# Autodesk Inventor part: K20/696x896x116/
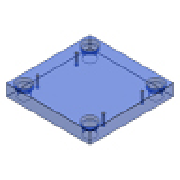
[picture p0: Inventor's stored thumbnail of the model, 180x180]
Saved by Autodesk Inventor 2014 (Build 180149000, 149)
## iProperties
IsCustomPart: 1
Created: 2009-11
Part Number: K20/696x896x116/
Material: DIN 1.1730
Description: Cavity Plate
Document SubType Name: Modeling
Designer: gaom
Standard Revision: 1
Manufacturer: HASCO
Language: en-US
Size Designation: 696x896x116/
Categories: <MemberInstance><Categories><Category DisplayName="Mold" InternalName="349578f2-f4d4-4954-8c09-8e99297a61c0" Mnemonic="MOLD"><Category DisplayName="Mold Plates"
Density: 7.82 g/cm^3
Appearance: Clear - Blue
Author: gaom
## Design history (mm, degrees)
sketch "Sketch1"
  geometry: L1 (-348, 448)-(348, 448); L2 (348, 448)-(348, -448); L3 (348, -448)-(-348, -448); L4 (-348, -448)-(-348, 448); 3 further points
  constraints: 8 end point, 2 midpoint, 2 parallel, 1 horizontal, 1 horizontal alignment, 1 perpendicular, 1 vertical alignment
  dimensions: "d126" = 696 distance between parallel lines of L2 L4 (= TW_); "d127" = 896 distance between parallel lines of L3 L1 (= TL)
extrude "Extrusion1" new body sketch "Sketch1" distance "d20" = 116 (= H_); taper "d30" = 0 deg
sketch "Sketch2"
  geometry: 6 further points
  dimensions: "d128" = 296 horizontal distance of point (0, 0) point (-296, 337) (= 0.5 x S1_W); "d129" = 337 vertical distance of point (0, 0) point (-296, 337) (= 0.5 x S1_L); "d130" = 396 vertical distance of point (0, 0) point (-296, 396) (= 0.5 x GP_L); "d131" = 296 horizontal distance of point (0, 0) point (-296, 396) (= 0.5 x GP_W); "d161" = 296 horizontal distance of point (0, 0) point (-296, -396) (= 0.5 x GP_W); "d162" = 396 vertical distance of point (0, 0) point (-296, -396) (= 0.5 x GP_L); "d163" = 296 horizontal distance of point (0, 0) point (296, 396) (= 0.5 x GP_W); "d164" = 396 vertical distance of point (0, 0) point (296, 396) (= 0.5 x GP_L); "d165" = 296 horizontal distance of point (296, -396) point (0, 0) (= 0.5 x GP_W); "d166" = 396 vertical distance of point (0, 0) point (296, -396) (= 0.5 x GP_L)
feature "Sculpt6"
workplane "Work Plane2"
workplane "Work Plane3"
workplane "Work Plane4"
workplane "Work Plane5"
workplane "Work Plane6"
workplane "Work Plane7"
workplane "Work Plane8"
workplane "Work Plane9"
feature "Sculpt109"
feature "Sculpt110"
feature "Sculpt111"
feature "Sculpt112"
feature "Sculpt113"
feature "Sculpt114"
feature "Sculpt115"
feature "Sculpt116"
feature "Sculpt117"
feature "Sculpt118"
feature "Sculpt119"
feature "Sculpt120"
feature "Sculpt121"
feature "Sculpt122"
feature "Sculpt123"
feature "Sculpt124"
feature "Sculpt125"
feature "Sculpt126"
feature "Sculpt127"
feature "Sculpt128"
sketch "Sketch3"
  geometry: L1 (-211.617, 350)-(211.617, 350); L2 (-220, -341.617)-(-220, 341.617); L3 (211.617, -350)-(-211.617, -350); L4 (220, 341.617)-(220, -341.617); A1 r 6 centre (216.464, 346.464) between (220, 341.617) and (211.617, 350); A2 r 6 centre (-216.464, 346.464) between (-211.617, 350) and (-220, 341.617); A3 r 6 centre (-216.464, -346.464) between (-220, -341.617) and (-211.617, -350); A4 r 6 centre (216.464, -346.464) between (211.617, -350) and (220, -341.617)
  constraints: 8 end point, 8 point on circle, 4 centre point
extrude "Extrusion2" cut sketch "Sketch3" distance "d189" = 120; taper "d190" = 0 deg
feature "Sculpt133"
thread "Thread1" dims "d191" = 0, "d192" = 0
feature "Sculpt134"
thread "Thread2" dims "d193" = 0, "d194" = 0
feature "Sculpt135"
thread "Thread3" dims "d195" = 0, "d196" = 0
feature "Sculpt136"
thread "Thread4" dims "d197" = 0, "d198" = 0
feature "Sculpt137"
thread "Thread5" dims "d199" = 0, "d200" = 0
feature "Sculpt138"
thread "Thread6" dims "d201" = 0, "d202" = 0
feature "Sculpt139"
thread "Thread7" dims "d203" = 0, "d204" = 0
feature "Sculpt140"
thread "Thread8" dims "d205" = 0, "d206" = 0
feature "Sculpt141"
body "Solid1"
hole "Hole1" sketch "Sketch2" diameter "d132" = 54 (= GP_d1); stored, may be unused: countersink angle "d136" = 90 deg, drill point angle "d138" = 0 deg; dims "d133" = 6, "d134" = 61 (= GP_d2), "d135" = 10.3 (= GP_k), "d137" = 116 (= H_)
hole "Hole2" sketch "Sketch2" diameter "d139" = 17.294; stored, may be unused: countersink angle "d143" = 90 deg, drill point angle "d145" = 118 deg; dims "d140" = 32 (= S1_h1), "d141" = 61 (= GP_d2), "d142" = 10.3 (= GP_k), "d144" = 45 (= S1_h2)
pattern_linear "Rectangular Pattern2" dims "d154" = 674 (computed from S1_L, Ns), "d157" = 592 (computed from S1_W, Nw)
hole "Hole3" sketch "Sketch2" diameter "d167" = 54 (= GP_d1); stored, may be unused: countersink angle "d171" = 90 deg, drill point angle "d173" = 0 deg; dims "d168" = 6, "d169" = 61 (= GP_d2), "d170" = 10.3 (= GP_k), "d172" = 116 (= H_)
hole "Hole4" sketch "Sketch2" diameter "d174" = 54 (= GP_d1); stored, may be unused: countersink angle "d178" = 90 deg, drill point angle "d180" = 0 deg; dims "d175" = 6, "d176" = 61 (= GP_d2), "d177" = 10.3 (= GP_k), "d179" = 116 (= H_)
hole "Hole5" sketch "Sketch2" diameter "d181" = 54 (= GP_d1); stored, may be unused: countersink angle "d185" = 90 deg, drill point angle "d187" = 0 deg; dims "d182" = 6, "d183" = 61 (= GP_d2), "d184" = 10.3 (= GP_k), "d186" = 116 (= H_)
chamfer "Chamfer1" distance "d158" = 0.5; stored, may be unused: second distance "d159" = 2, angle "d160" = 45 deg
feature "Surface6"
body "Srf6"
feature "Surface109"
body "Srf109"
feature "Surface110"
body "Srf110"
feature "Surface111"
body "Srf111"
feature "Surface112"
body "Srf112"
feature "Surface113"
body "Srf113"
feature "Surface114"
body "Srf114"
feature "Surface115"
body "Srf115"
feature "Surface116"
body "Srf116"
feature "Surface117"
body "Srf117"
feature "Surface118"
body "Srf118"
feature "Surface119"
body "Srf119"
feature "Surface120"
body "Srf120"
feature "Surface121"
body "Srf121"
feature "Surface122"
body "Srf122"
feature "Surface123"
body "Srf123"
feature "Surface124"
body "Srf124"
feature "Surface125"
body "Srf125"
feature "Surface126"
body "Srf126"
feature "Surface127"
body "Srf127"
feature "Surface128"
body "Srf128"
feature "Surface133"
body "Srf133"
feature "Surface134"
body "Srf134"
feature "Surface135"
body "Srf135"
feature "Surface136"
body "Srf136"
feature "Surface137"
body "Srf137"
feature "Surface138"
body "Srf138"
feature "Surface139"
body "Srf139"
feature "Surface140"
body "Srf140"
feature "Surface141"
body "Srf141"
other parameters: "TL" = 896 [user parameter; used in 1 equation term], "TW_" = 696 [user parameter; used in 1 equation term], "H_" = 116 [user parameter; used in 5 equation terms], "GP_W" = 592 [user parameter; used in 4 equation terms], "GP_d1" = 54 [user parameter; used in 4 equation terms], "GP_d2" = 61 [user parameter; used in 5 equation terms], "GP_k" = 10.3 [user parameter; used in 5 equation terms], "S1_L" = 674 [user parameter; used in 2 equation terms], "S1_W" = 592 [user parameter; used in 2 equation terms], "GP_L" = 792 [user parameter; used in 4 equation terms], "S1_h2" = 45 [user parameter; used in 1 equation term], "S1_h1" = 32 [user parameter; used in 1 equation term], "L" = 896 [user parameter], "W_" = 696 [user parameter], "d188" = -36.41956
